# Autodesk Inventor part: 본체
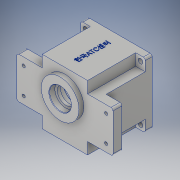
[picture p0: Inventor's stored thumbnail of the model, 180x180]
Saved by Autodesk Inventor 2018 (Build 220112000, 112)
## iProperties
Created: 2020-07
Part Number: 본체
Material: 알루미늄 6061
Document SubType Name: Modeling
Designer: Admin
Density: 2.7 g/cm^3
Appearance: 알루미늄 - 평지
Mass: 876.486 g
Surface Area: 793.573 cm^2
Volume: 324.624 cm^3
Author: Admin
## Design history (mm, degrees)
sketch "스케치1"
  geometry: L1 (-47, -47)-(47, -47); L2 (47, -47)-(47, 47); L3 (47, 47)-(-47, 47); L4 (-47, 47)-(-47, -47); L5 (-47, -47)-(47, 47); L6 (47, -47)-(-47, 47); 1 further point
  constraints: 12 end point, 2 midpoint, 2 parallel, 1 horizontal, 1 perpendicular
  dimensions: "d0" = 94 distance of L2.end L3.end; "d1" = 94 distance of L3.end L1.start
extrude "돌출1" new body sketch "스케치1" distance "d2" = 80; taper "d3" = 0 deg
sketch "스케치2"
  geometry: L1 (-70, -30)-(70, -30); L2 (70, -30)-(70, 30); L3 (70, 30)-(-70, 30); L4 (-70, 30)-(-70, -30); L5 (-70, -30)-(70, 30); L6 (70, -30)-(-70, 30); 1 further point
  constraints: 12 end point, 2 midpoint, 2 parallel, 1 horizontal, 1 perpendicular
  dimensions: "d4" = 140 distance of L2.end L3.end; "d5" = 60 distance of L1.end L2.end
extrude "돌출2" join sketch "스케치2" distance "d6" = 13; taper "d7" = 0 deg
sketch "스케치3"
  geometry: L1 (47, 30)-(47, 47) reference; L2 (47, 47)-(-47, 47) reference; L3 (-47, 47)-(-47, 30) reference; L4 (-47, 30)-(-70, 30) reference; L5 (-70, 30)-(-70, -30) reference; L6 (-70, -30)-(-47, -30) reference; L7 (-47, -30)-(-47, -47) reference; L8 (-47, -47)-(47, -47) reference; L9 (47, -47)-(47, -30) reference; L10 (47, -30)-(70, -30) reference; L11 (70, -30)-(70, 30) reference; L12 (70, 30)-(47, 30) reference; L13 (47, 47)-(-47, 47) reference; L14 (-47, 47)-(-33, 47); L15 (-33, 47)-(-33, 30); L16 (-33, 30)-(-47, 30); L17 (-47, 30)-(-47, 47); L18 (47, 47)-(33, 47); L19 (33, 47)-(33, 30); L20 (33, 30)-(47, 30); L21 (47, 30)-(47, 47); L22 (47, -47)-(47, 47) reference; L23 (47, -47)-(33, -47); L24 (33, -47)-(33, -30); L25 (33, -30)-(47, -30); L26 (47, -30)-(47, -47); L27 (-47, -47)-(47, -47) reference; L28 (-47, -47)-(-33, -47); L29 (-33, -47)-(-33, -30); L30 (-33, -30)-(-47, -30); L31 (-47, -30)-(-47, -47); L32 (-98, 0)-(98, 0) reference; L33 (0, -65.8)-(0, 65.8) reference; 1 further point
  constraints: 32 end point, 8 parallel, 4 horizontal, 4 perpendicular, 2 collinear, 4 other
  dimensions: "d8" = 66 distance between parallel lines of L19 L15; "d10" = 60 distance between parallel lines of L25 L20
extrude "돌출3" cut sketch "스케치3" distance "d11" = 70; taper "d12" = 0 deg
sketch "스케치4"
  geometry: L1 (0, -65.8)-(0, 65.8) reference; C1 r 27.5 at (0, 11); 1 further point
  constraints: 1 centre point, 1 point on line
  dimensions: "d13" = 11 distance of point (0, 0) C1.centre; "d14" = 55 diameter of C1
extrude "돌출4" join sketch "스케치4" distance "d15" = 7; taper "d16" = 0 deg
sketch "스케치5"
  geometry: C1 r 43 at (0, 0); 1 further point
  constraints: 1 centre point, 1 coincident
  dimensions: "d17" = 86 diameter of C1
extrude "돌출5" cut sketch "스케치5" distance "d18" = 9; taper "d19" = 0 deg
sketch "스케치6"
  geometry: C1 r 43 at (0, 0) reference; C2 r 40 at (0, 0); 1 further point
  constraints: 1 centre point, 1 coincident
  dimensions: "d20" = 80 diameter of C2
extrude "돌출6" cut sketch "스케치6" distance "d21" = 62; taper "d22" = 0 deg
sketch "스케치7"
  geometry: L1 (0, -65.8)-(0, 65.8) reference; C1 r 27.5 at (0, 11) reference; A1 r 15 centre (0, -20) between (-8.978, -7.984) and (8.978, -7.984); A2 r 21 centre (0, 11) between (8.978, -7.984) and (-8.978, -7.984); 1 further point
  constraints: 4 point on circle, 2 centre point, 1 coincident, 1 point on line
  dimensions: "d23" = 20 distance of point (0, 0) A1.centre; "d24" = 42 diameter of A2; "d25" = 30 diameter of A1
extrude "돌출7" join sketch "스케치7" distance "d26" = 7; taper "d27" = 0 deg
sketch "스케치8"
  geometry: C1 r 17.5 at (0, 11); A1 r 21 centre (0, 11) between (8.978, -7.984) and (-8.978, -7.984) reference; 1 further point
  constraints: 1 centre point, 1 coincident
  dimensions: "d28" = 35 diameter of C1
extrude "돌출8" cut sketch "스케치8" distance "d29" = 10; taper "d30" = 0 deg
sketch "스케치9"
  geometry: C1 r 27.5 at (0, 0) reference; C2 r 16 at (0, 0); 1 further point
  constraints: 1 centre point, 1 coincident
  dimensions: "d31" = 32 diameter of C2
extrude "돌출9" cut sketch "스케치9" distance "d32" = 8.3; taper "d33" = 0 deg
sketch "스케치10"
  geometry: C1 r 16 at (0, 0) reference; C2 r 12.5 at (0, 0); 1 further point
  constraints: 1 centre point, 1 coincident
  dimensions: "d34" = 25 diameter of C2
extrude "돌출10" cut sketch "스케치10" stored distance "d35" = 8.3; taper "d36" = 0 deg
sketch "스케치11"
  geometry: C1 r 11 at (0, -20); A1 r 15 centre (0, -20) between (-8.978, -7.984) and (8.978, -7.984) reference; 1 further point
  constraints: 1 centre point, 1 coincident
  dimensions: "d37" = 22 diameter of C1
extrude "돌출11" cut sketch "스케치11" distance "d38" = 7; taper "d39" = 0 deg
sketch "스케치12"
  geometry: C1 r 11 at (0, 0) reference; C2 r 9.5 at (0, 0); 1 further point
  constraints: 1 centre point, 1 coincident
  dimensions: "d40" = 19 diameter of C2
extrude "돌출12" cut sketch "스케치12" distance "d41" = 3; taper "d42" = 0 deg
sketch "스케치13" dims "d43" = 72
  geometry: L1 (98, 0)-(-98, 0) reference; L2 (0, -65.8)-(0, 65.8) reference; L3 (-36, 4)-(-36.332, 4); L4 (-36, 4)-(-39.799, 4); L5 (-36, -4)-(-39.799, -4); L6 (36, 4)-(36.332, 4); L7 (36, 4)-(39.799, 4); L8 (36, -4)-(39.799, -4); A1 r 40 centre (0, 0) between (-39.799, 4) and (-39.799, -4) reference; A2 r 4 centre (-36, 0) between (-36, -4) and (-36, 4); A3 r 40 centre (0, 0) between (-39.799, 4) and (-39.799, -4); A4 r 4 centre (36, 0) between (36, 4) and (36, -4); A5 r 40 centre (0, 0) between (39.799, -4) and (39.799, 4); 2 further points
  constraints: 12 end point, 10 point on circle, 6 symmetric about line, 4 centre point, 3 tangent, 2 coincident, 2 horizontal, 1 horizontal alignment, 1 parallel, 1 point on line, 4 other
  dimensions: "d44" = 8 diameter of A2
extrude "돌출13" join sketch "스케치13" stored distance "d47" = 0; taper "d48" = 0 deg
chamfer "모따기1" distance "d49" = 1; stored, may be unused: second distance "d50" = 2, angle "d51" = 45 deg
chamfer "모따기2" distance "d52" = 0.8; stored, may be unused: second distance "d53" = 2, angle "d54" = 30 deg
fillet "모깎기1" dims "d55" = 3
fillet "모깎기2" dims "d56" = 3
sketch "스케치14"
  geometry: L1 (33, 97.4)-(33, -24.4) reference; L2 (77, 80)-(-11, 80) reference; 2 further points
  constraints: 1 point on line, 1 other
  dimensions: "d57" = 40 distance from line of point (33, 40) L2
feature "엠보싱1" sketch "스케치14" dims "d0" = 94, "d1" = 94, "d58" = 0.5, "d59" = 0
fillet "모깎기3" dims "d60" = 3
sketch "스케치15"
  geometry: L1 (98, 0)-(-98, 0) reference; L2 (0, -65.9)-(0, 66.4) reference; 5 further points
  constraints: 4 symmetric about line
  dimensions: "d61" = 120 distance of point (-60, 19) point (60, 19); "d62" = 38 distance of point (60, -19) point (60, 19)
hole "구멍1" sketch "스케치15" at (-60, 19), (60, 19), (60, -19), (-60, -19) diameter "d63" = 4.5; stored, may be unused: countersink angle "d67" = 90 deg, drill point angle "d69" = 118 deg; dims "d64" = 6, "d65" = 10, "d66" = 5, "d68" = 8
sketch "스케치16"
  geometry: L1 (98, 0)-(-98, 0) reference; L2 (0, -65.9)-(0, 66.4) reference; 5 further points
  constraints: 4 symmetric about line
  dimensions: "d70" = 80 distance of point (40, 40) point (-40, 40); "d71" = 80 distance of point (40, -40) point (40, 40)
hole "구멍2" sketch "스케치16" at (-40, 40), (40, 40), (40, -40), (-40, -40) diameter "d72" = 7; stored, may be unused: countersink angle "d76" = 90 deg, drill point angle "d78" = 118 deg; dims "d73" = 6, "d74" = 10, "d75" = 5, "d77" = 10
sketch "스케치17"
  geometry: A1 r 4 centre (-36, 0) between (-36, -4) and (-36, 4) reference; A2 r 4 centre (36, 0) between (36, 4) and (36, -4) reference; 3 further points
  constraints: 2 coincident
hole "구멍3" sketch "스케치17" at (-36, 0), (36, 0) diameter "d79" = 3.242; stored, may be unused: countersink angle "d83" = 90 deg, drill point angle "d85" = 118 deg; dims "d80" = 7, "d81" = 10, "d82" = 5, "d84" = 9
fillet "모깎기4" dims "d86" = 3
node "솔리드1"
node "투영된 루프1"
